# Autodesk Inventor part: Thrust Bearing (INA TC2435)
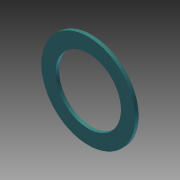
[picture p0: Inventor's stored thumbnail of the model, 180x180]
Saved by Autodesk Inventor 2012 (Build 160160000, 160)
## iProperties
Created: 2010-12
Part Number: Thrust Bearing (INA TC2435)
Document SubType Name: Modeling
Designer: Alex
Density: 7.85 g/cm^3
Material: Steel
Mass: 19.0541 g
Surface Area: 30.3035 cm^2
Volume: 2.42727 cm^3
Author: Alex
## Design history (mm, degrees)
sketch "Sketch1"
  geometry: C1 r 27.483 at (0, 0); 2 further points
  constraints: 1 centre point
  dimensions: "d0" = 54.9656 diameter of C1
extrude "Extrusion1" new body sketch "Sketch1" distance "d1" = 1.9812; taper "d2" = 0 deg
hole "Hole1" diameter "d5" = 38.227; stored, may be unused: countersink angle "d9" = 82 deg, drill point angle "d11" = 118 deg; dims "d3" = 25.4, "d4" = 25.4, "d6" = 19.05, "d7" = 9.525, "d8" = 6.35, "d10" = 25.4
body "Solid1"
